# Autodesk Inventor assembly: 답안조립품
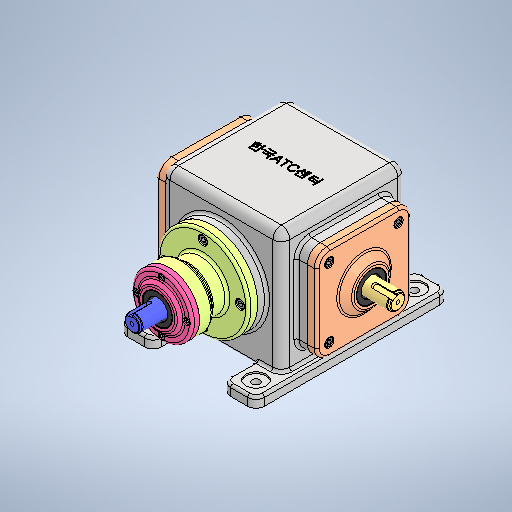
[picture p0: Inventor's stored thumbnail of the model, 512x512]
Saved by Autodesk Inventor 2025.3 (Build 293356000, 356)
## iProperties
Created: 2026-01
Part Number: 답안조립품
Document SubType Name: Assembly
Designer: pc6
Author: pc6
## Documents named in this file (16)
- C:\Users\pc6\Desktop\760103V1008\답안조립품.iam
- C:\Users\pc6\Desktop\760103V1008\본체.ipt
- C:\Users\pc6\Desktop\760103V1008\종동축\종동축\종동축.ipt
- C:\Users\pc6\Desktop\760103V1008\평행 키 6x6x18\평행 키 6x6x18\평행 키 6x6x18.ipt
- C:\Users\pc6\Desktop\760103V1008\베벨 기어(종동)\베벨 기어(종동)\베벨 기어(종동).ipt
- C:\Users\pc6\Desktop\760103V1008\칼라\칼라\칼라.ipt
- C:\Users\pc6\Desktop\760103V1008\테이퍼 롤러 베어링 30204K\테이퍼 롤러 베어링 30204K\테이퍼 롤러 베어링 30204K.ipt
- C:\Users\pc6\Desktop\760103V1008\측면 커버\측면 커버\측면 커버.ipt
- C:\Users\pc6\Desktop\760103V1008\오일 실 20 35 8\오일 실 20 35 8\오일 실 20 35 8.ipt
- C:\Users\pc6\Desktop\760103V1008\구동축\구동축\구동축.ipt
- C:\Users\pc6\Desktop\760103V1008\베어링 하우징\베어링 하우징\베어링 하우징.ipt
- C:\Users\pc6\Desktop\760103V1008\베벨 기어(구동)\베벨 기어(구동)\베벨 기어(구동).ipt
- C:\Users\pc6\Desktop\760103V1008\엔드캡\엔드캡\엔드캡.ipt
- C:\Users\pc6\Desktop\760103V1008\하우징 커버\하우징 커버\하우징 커버.ipt
- C:\Users\pc6\Desktop\760103V1008\6각 구멍붙이 볼트 M6x12\6각 구멍붙이 볼트 M6x12\6각 구멍붙이 볼트 M6x12.ipt
- C:\Users\pc6\Desktop\760103V1008\6각 구멍붙이 볼트 M4x10\6각 구멍붙이 볼트 M4x10\6각 구멍붙이 볼트 M4x10.ipt
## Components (19 placed, 4 different names)
1. 구동축:1
2. 하우징 커버:1
3. 6각 구멍붙이 볼트 M6x12:1
4. 6각 구멍붙이 볼트 M6x12:2
5. 6각 구멍붙이 볼트 M6x12:3
6. 6각 구멍붙이 볼트 M6x12:4
7. 6각 구멍붙이 볼트 M6x12:5
8. 6각 구멍붙이 볼트 M6x12:6
9. 6각 구멍붙이 볼트 M6x12:7
10. 6각 구멍붙이 볼트 M6x12:8
11. 6각 구멍붙이 볼트 M6x12:9
12. 6각 구멍붙이 볼트 M6x12:10
13. 6각 구멍붙이 볼트 M6x12:11
14. 6각 구멍붙이 볼트 M6x12:12
15. 6각 구멍붙이 볼트 M6x12:13
16. 6각 구멍붙이 볼트 M4x10:1
17. 6각 구멍붙이 볼트 M4x10:2
18. 6각 구멍붙이 볼트 M4x10:3
19. 6각 구멍붙이 볼트 M4x10:4
